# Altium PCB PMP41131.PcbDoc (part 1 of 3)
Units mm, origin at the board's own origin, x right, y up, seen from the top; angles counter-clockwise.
Board outline 53.98 x 39 mm, 6 copper layers (Top Layer, Signal Layer 1, Signal Layer 2, Signal Layer 3, Signal Layer 4, Bottom Layer), stack 1.835 mm thick; 91 components, 60 nets, 285 pads, 252 vias.
Unrouted connection lines stored in the file: 18.
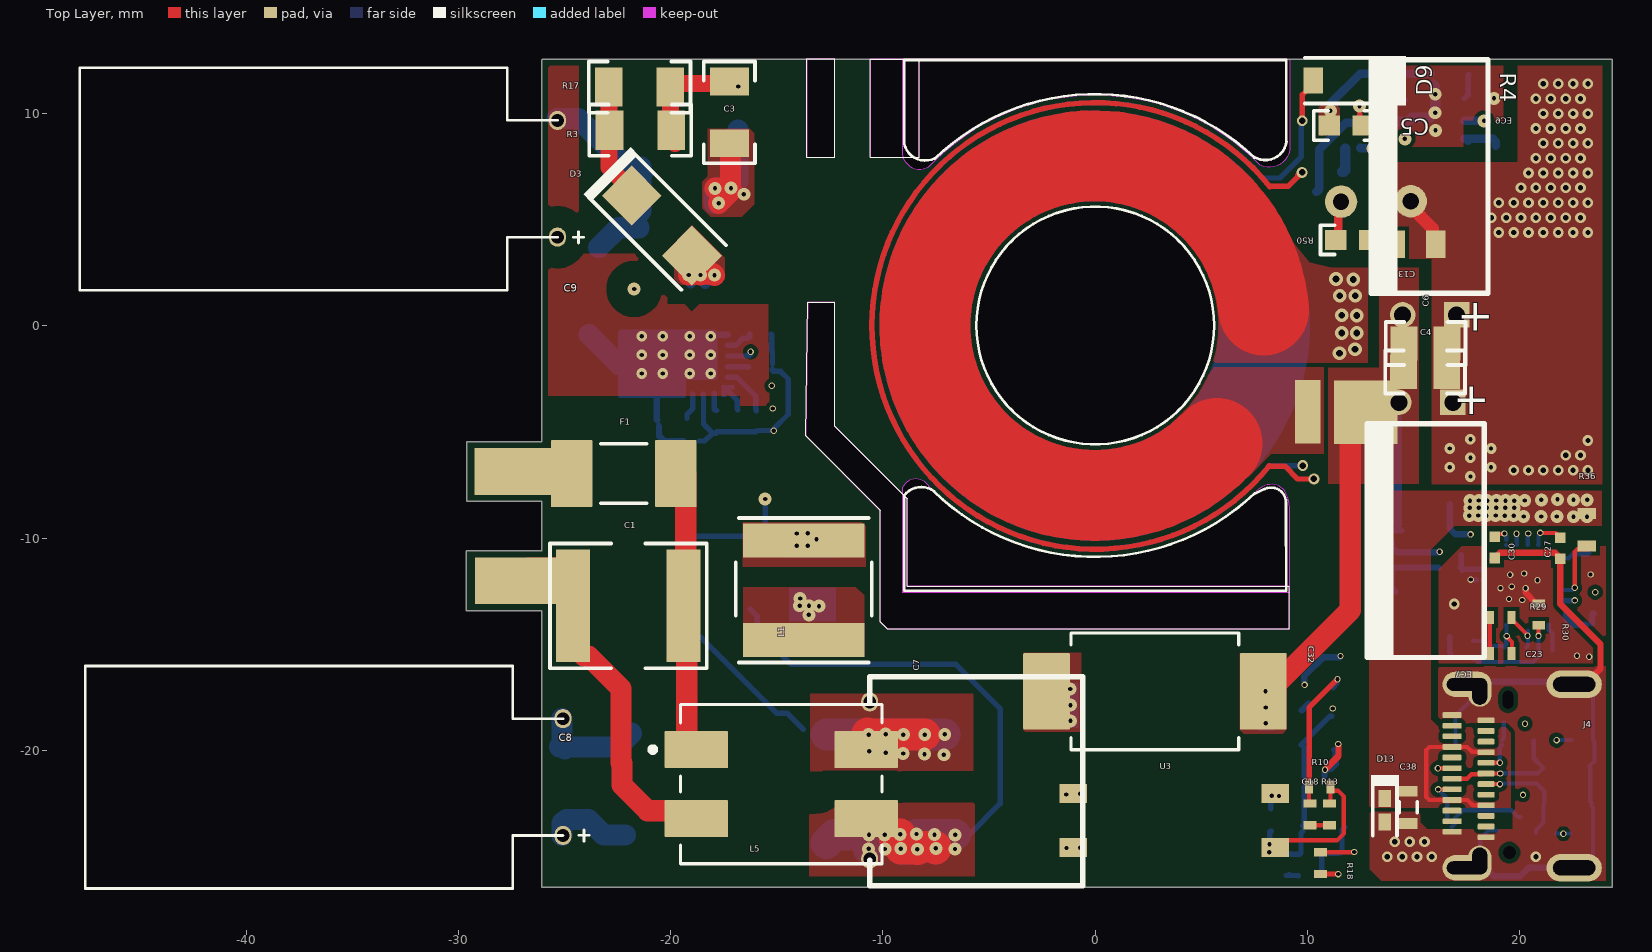
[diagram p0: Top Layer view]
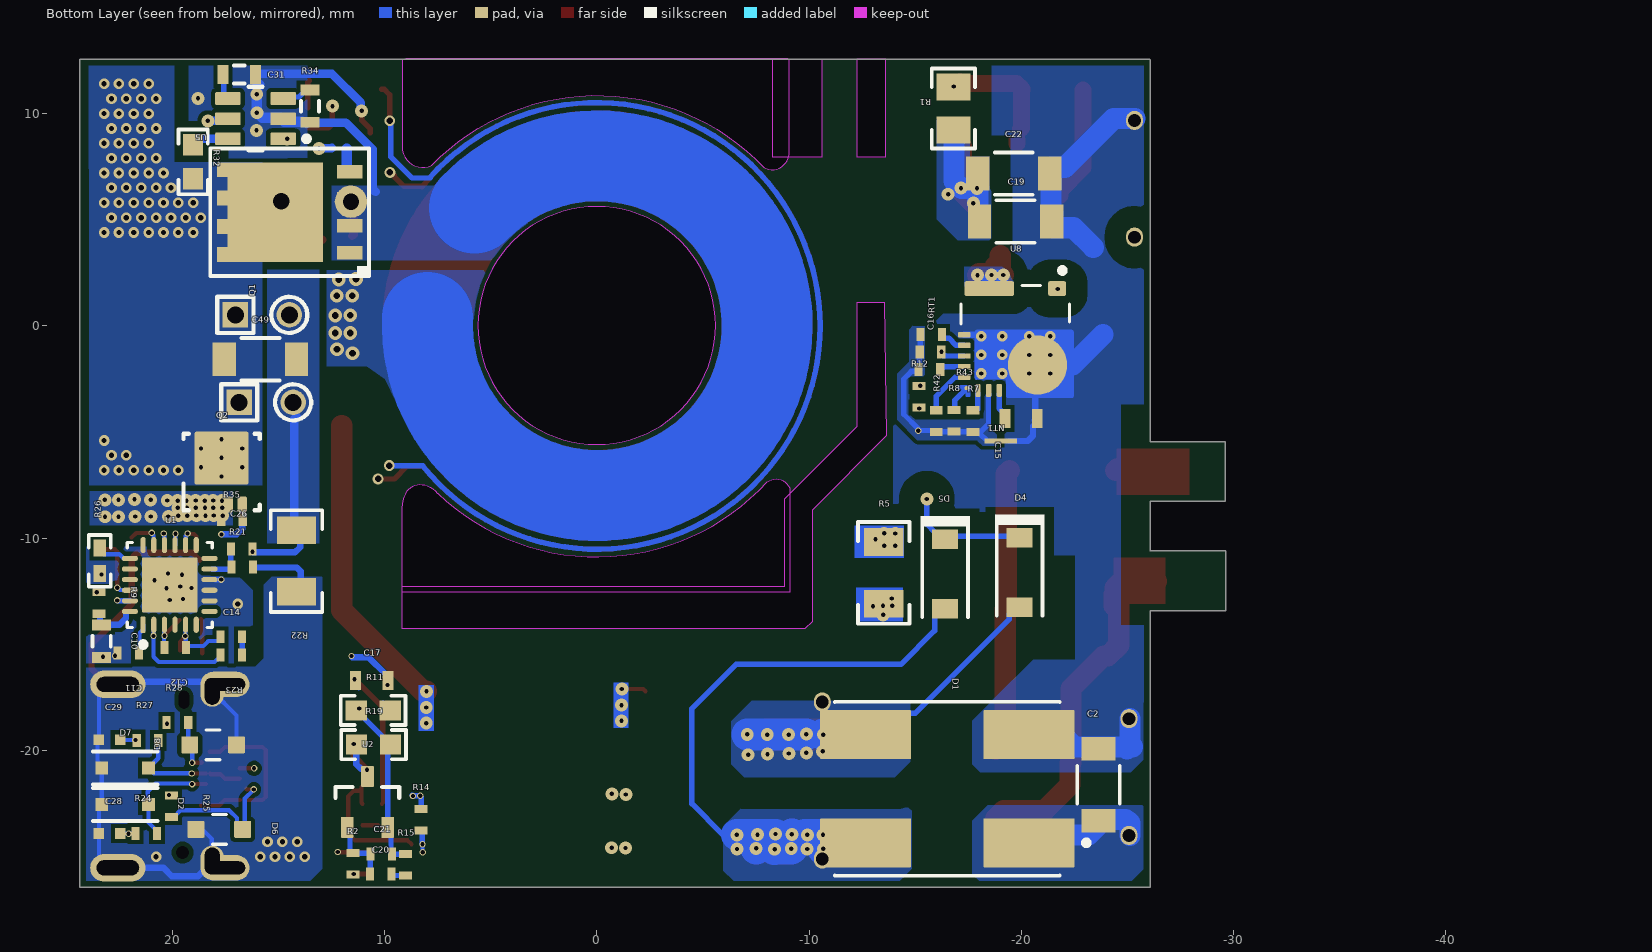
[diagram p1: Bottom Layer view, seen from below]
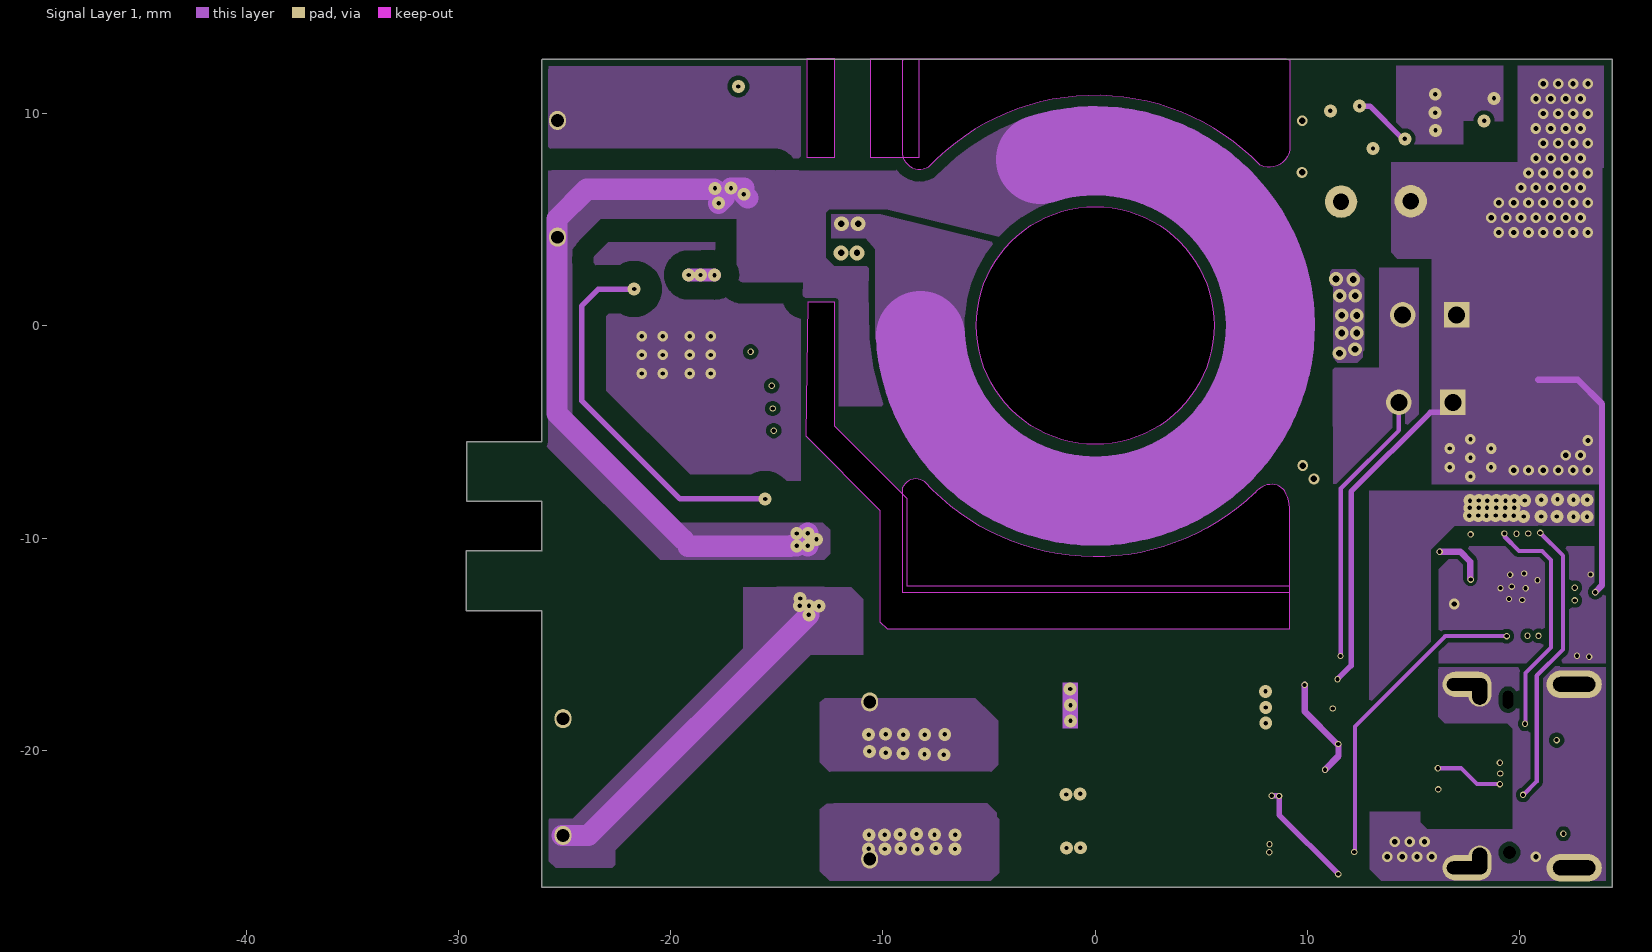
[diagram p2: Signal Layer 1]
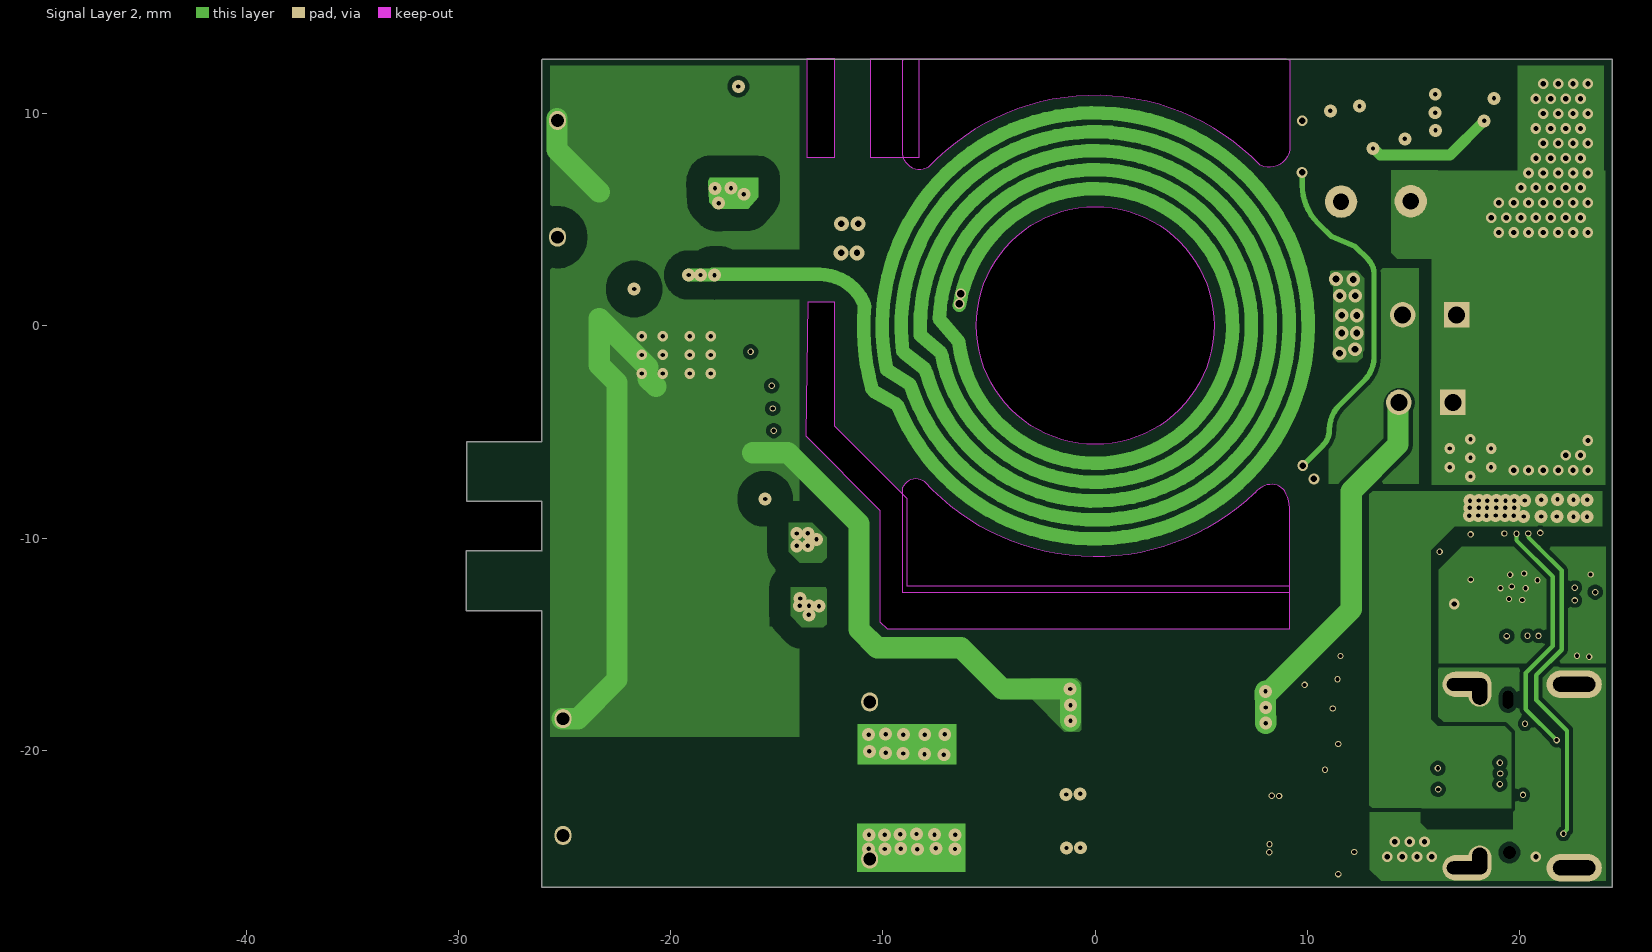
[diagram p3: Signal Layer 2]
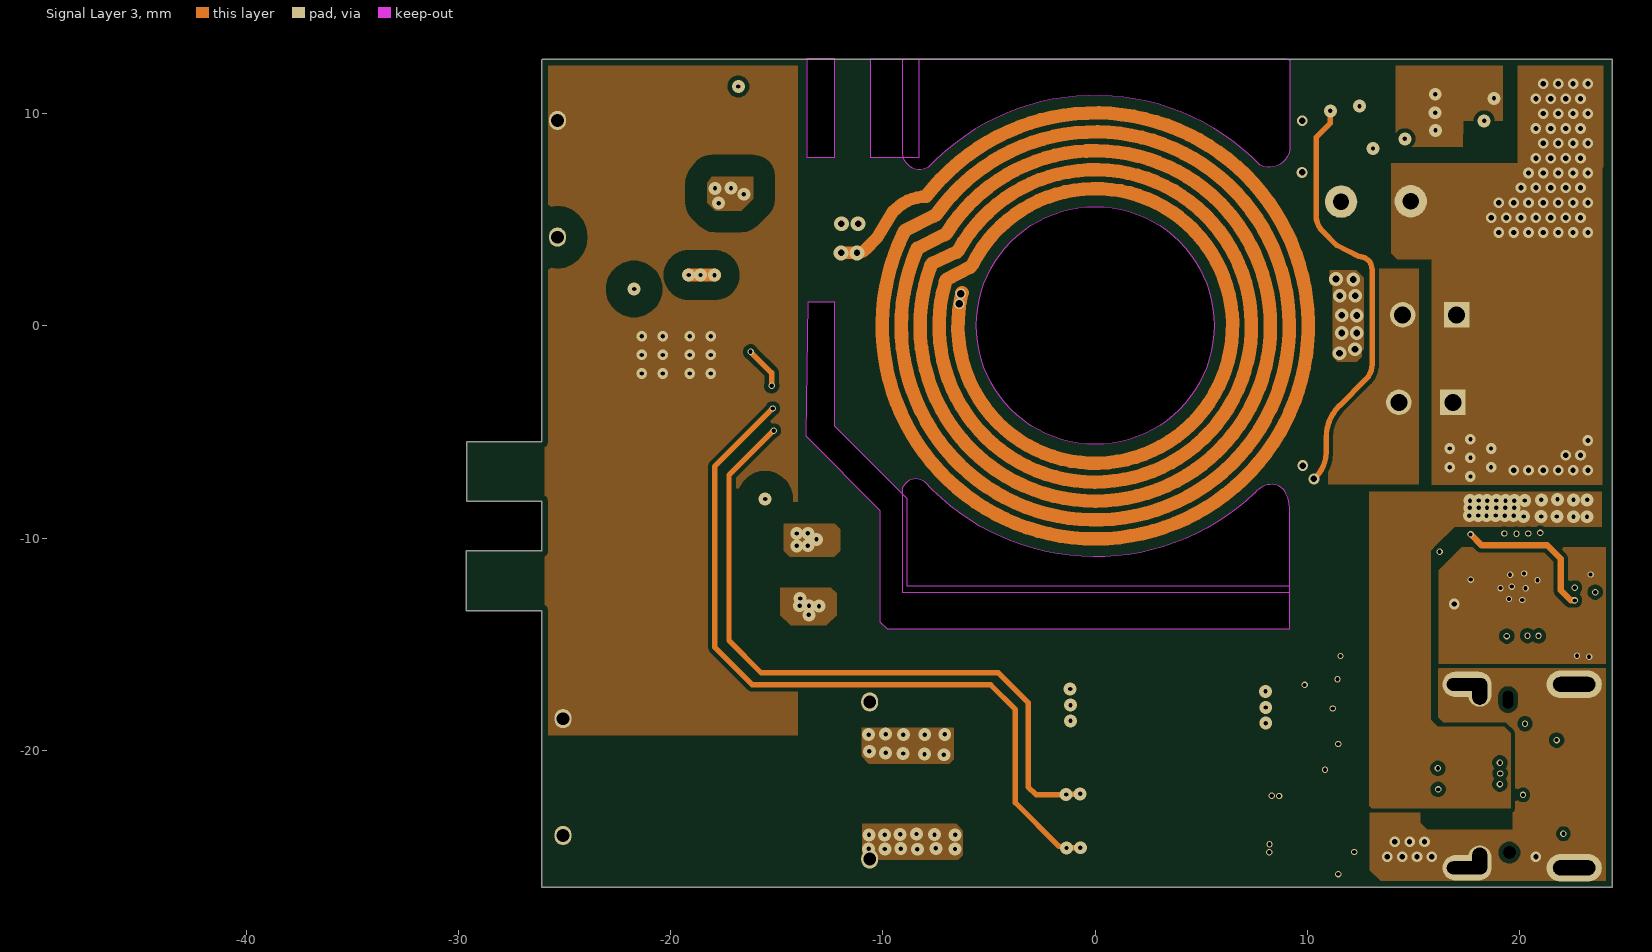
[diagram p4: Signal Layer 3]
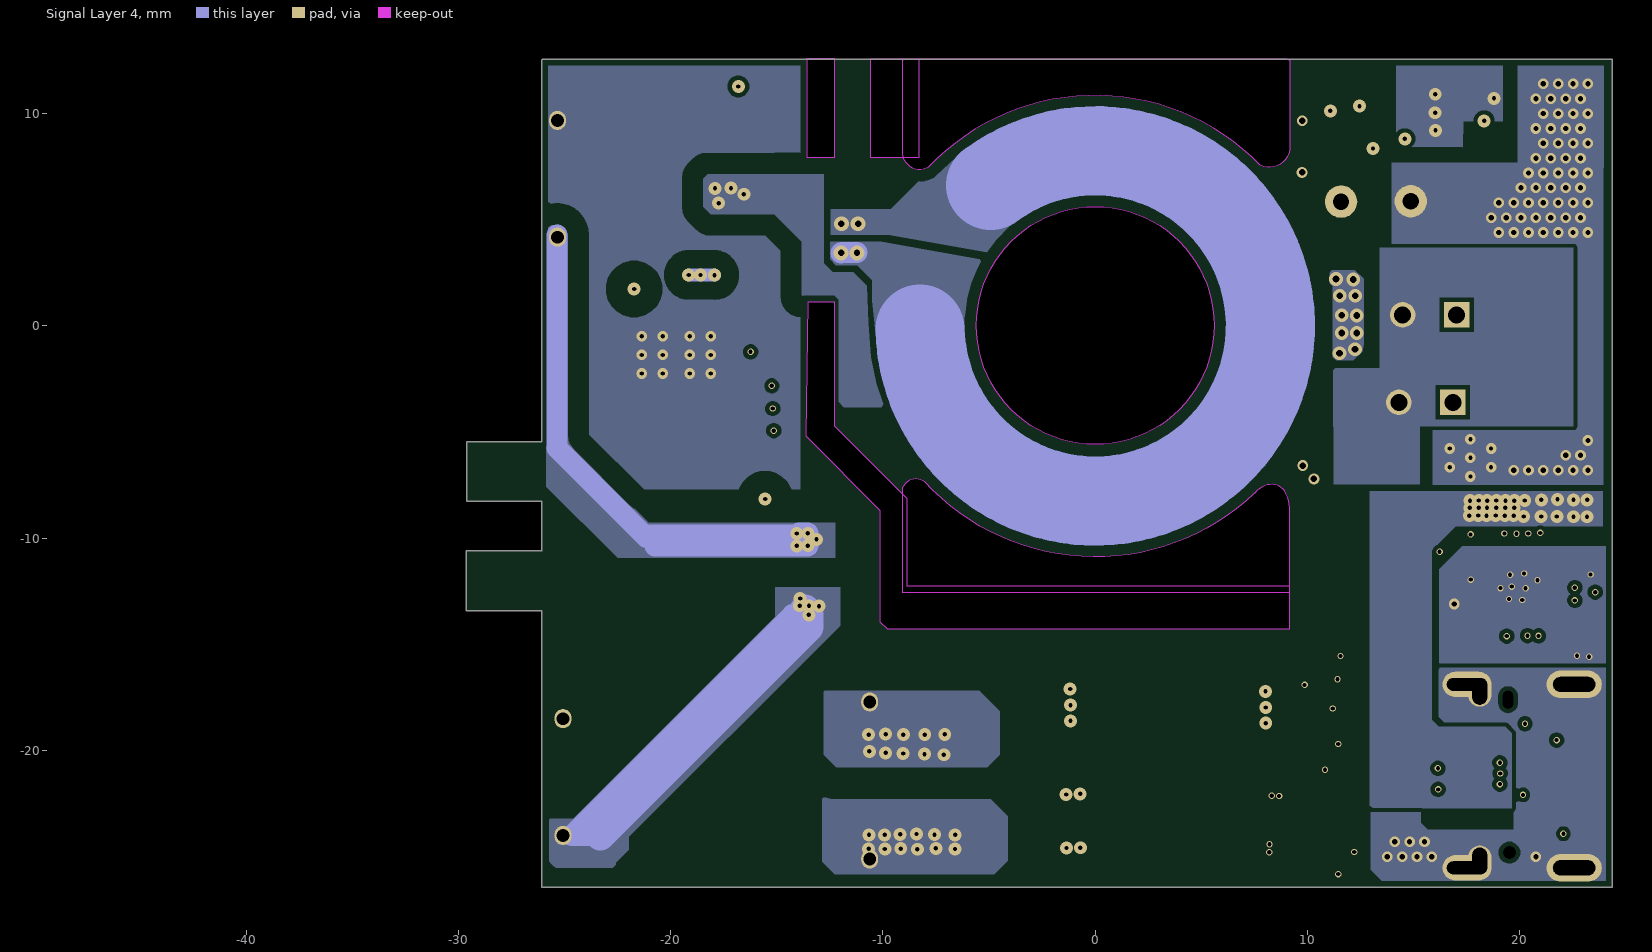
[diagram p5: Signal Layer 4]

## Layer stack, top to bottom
Top Solder: solder mask 0.0127, Solder Resist, Dk 3.5
Top Layer: signal copper 0.14
Dielectric 1: prepreg 0.1778, FR-4 High Tg, Dk 4.2
Signal Layer 1: signal copper 0.07
Dielectric 2: core 0.3556, FR-4 High Tg, Dk 4.2
Signal Layer 2: signal copper 0.07
Dielectric 4: prepreg 0.2083, FR-4 High Tg, Dk 4.2
Signal Layer 3: signal copper 0.07
Dielectric 5: core 0.3556, FR-4 High Tg, Dk 4.2
Signal Layer 4: signal copper 0.07
Dielectric 3: prepreg 0.1778, FR-4 High Tg, Dk 4.2
Bottom Layer: signal copper 0.14
Bottom Solder: solder mask 0.0127, Solder Resist, Dk 3.5

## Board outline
-29.63,-13.41 -29.63,-10.6 -26.08,-10.6 -26.06,-10.59 -26.06,-8.26 -29.61,-8.26 -29.61,-5.45 -26.06,-5.45 -26.06,12.543 -26.04,12.554 24.35,12.554 24.35,-26.45 -26.06,-26.45 -26.06,-26.436 -26.06,-13.41
cut-out: -7.857,7.483 cw(c-8.275,8.14) -9.018,7.907 -9.064,8.055 -9.064,8.579 -9.064,12.52 -9,12.584 9,12.584 9.166,12.52 9.166,8.436 cw(c8.194,8.442) 7.78,7.563 ccw(c0,0.02)
cut-out: -9.081,-12.539 9.155,-12.539 9.155,-8.567 ccw(c7.755,-8.547) 8.922,-7.773 ccw(c8.333,-8.198) 8.461,-7.483 ccw(c8.296,-8.309) 7.977,-7.529 ccw(c8.435,-8.63) 7.503,-7.887 7.498,-7.891 cw(c0,0.02) -8.036,-7.345 ccw(c-8.449,-7.894) -9.081,-7.624
cut-out: -10.227,34.327 cw(c-10.648,35.304) -11.685,35.069 -11.698,35.107 -11.698,39.037 -11.634,39.101 6.366,39.101 6.43,39.037 6.43,35.231 6.439,35.189 cw(c5.384,35.325) 4.89,34.383 4.825,34.397 ccw(c-2.634,26.537)
cut-out: 0,-5.58 cw(c0,0.02) -5.6,0.02 cw(c0,0.02) 0,5.62 cw(c0,0.02) 5.6,0.02 cw(c0,0.02)
cut-out: 0,-5.58 cw(c0,0.02) -5.6,0.02 cw(c0,0.02) 0,5.62 cw(c0,0.02) 5.6,0.02 cw(c0,0.02)
cut-out: -10.6,12.56 -10.6,7.94 -8.29,7.94 -8.29,12.56
cut-out: -13.59,12.592 -13.59,7.95 -12.26,7.95 -12.26,12.592
cut-out: -13.645,-5.18 -10.14,-8.685 -10.14,-13.925 -9.79,-14.275 9.15,-14.275 9.15,-12.265 -8.86,-12.265 -8.86,-8.145 -12.28,-4.725 -12.28,1.125 -13.548,1.125

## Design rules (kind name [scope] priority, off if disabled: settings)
AcuteAngle [All] p1: minimum=4.50000000000000E+0001 checktracksonly=FALSE
AssemblyTestPointUsage [All] p1: valid=2
BoardOutlineClearance BoardOutlineClearance_MountingHoles [OnCopper and InComponentClass('Mounting Holes')] p1: gap=0.3 ignorepadtopadclearanceinfootprint=FALSE
BoardOutlineClearance BoardOutlineClearance_Poly [OnCopper and IsPoly] p2: gap=0.3 ignorepadtopadclearanceinfootprint=FALSE
BoardOutlineClearance [OnCopper and Not InComponentClass('Logo') and not InComponentClass('FiducialMark') and not InRegion(1000,500,4000,800) and not InPoly] p3: gap=0.3 ignorepadtopadclearanceinfootprint=FALSE
Clearance Clearance_8 [InNamedPolygon('SIGNAL_LAYER_4_VBUS_P366')] p1: gap=0.55 ignorepadtopadclearanceinfootprint=FALSE
Clearance Clearance_7 [InNamedPolygon('SIGNAL_LAYER_1_VBUS_P372')] p2: gap=0.55 ignorepadtopadclearanceinfootprint=FALSE
Clearance Clearance_6 [InNamedPolygon('SIGNAL_LAYER_1_VBUS_P373')] p3: gap=0.55 ignorepadtopadclearanceinfootprint=FALSE
Clearance Clearance_5 [InNamedPolygon('SIGNAL_LAYER_4_VBUS_P371')] p4: gap=0.55 ignorepadtopadclearanceinfootprint=FALSE
Clearance Clearance_4 [InNamedPolygon('SIGNAL_LAYER_4_VBUS_P371')] p5: gap=0.55 ignorepadtopadclearanceinfootprint=FALSE
Clearance Clearance_2 [InNamedPolygon('SIGNAL_LAYER_1_VBUS_P373')] p6: gap=0.55 ignorepadtopadclearanceinfootprint=FALSE
Clearance [InNamedPolygon('SIGNAL_LAYER_1_VBUS_P373')] p7: gap=0.55 ignorepadtopadclearanceinfootprint=FALSE
Clearance Clearance_3 [InNamedPolygon('SIGNAL_LAYER_1_VBUS_P373')] p8: gap=0.6 ignorepadtopadclearanceinfootprint=FALSE
Clearance Clearance_VAC_PGND [InNetClass('VAC') vs InNetClass('PGND')] p9: gap=2 ignorepadtopadclearanceinfootprint=TRUE
Clearance Clearance_HV_PGND [InNetClass('High Voltage') vs InNetClass('PGND')] p10: gap=1.016 ignorepadtopadclearanceinfootprint=TRUE
Clearance Clearance_SW_PGND [InNetClass('Switch Node') vs InNetClass('PGND')] p11: gap=0.864 ignorepadtopadclearanceinfootprint=TRUE
Clearance Clearance_AC_AC [InNetClass('VAC') vs InNetClass('VAC')] p12: gap=1.5 ignorepadtopadclearanceinfootprint=TRUE
Clearance Clearance_PGND_SGND [InNetClass('PGND') vs InNetClass('SGND')] p13: gap=4.064 ignorepadtopadclearanceinfootprint=TRUE
Clearance Clearance_HV_LV [InNetClass('High Voltage') vs InNetClass('Low Voltage')] p14: gap=0.864 ignorepadtopadclearanceinfootprint=TRUE
Clearance Clearance_SW_LV_1 [InNetClass('Switch Node') vs InNetClass('Low Voltage')] p15: gap=0.864 ignorepadtopadclearanceinfootprint=TRUE
Clearance Clearance_SW_HV [InNetClass('Switch Node') vs InNetClass('High Voltage')] p16: gap=0.864 ignorepadtopadclearanceinfootprint=TRUE
Clearance Clearance_1 [All] p17: gap=0.2 ignorepadtopadclearanceinfootprint=TRUE
Clearance Clearance_Keepouts [((IsTrack Or IsArc) And Not InPoly) And IsFree and IsKeepOut vs ((IsTrack Or IsArc) And Not InPoly) And IsFree and IsKeepOut] p18: gap=0.254 ignorepadtopadclearanceinfootprint=FALSE
Clearance Clearance_Poly [InPolygon] p19: gap=0.254 ignorepadtopadclearanceinfootprint=TRUE
Clearance Clearance_FiducialMark [IsKeepOut and InComponentClass('FiducialMark') vs IsPad and InComponentClass('FiducialMark')] p20: gap=0.254 ignorepadtopadclearanceinfootprint=FALSE
ComponentClearance ComponentClearance_MountingHoles_FiducialMarks [InComponentClass('Mounting Holes') vs InComponentClass('FiducialMark')] p1: gap=0.2 collisioncheckmode=3 verticalgap=0.2 showdistances=FALSE
ComponentClearance ComponentClearance_Shunt [InComponentClass('Header') vs InComponentClass('Shunt')] p2: gap=0 collisioncheckmode=3 verticalgap=0 showdistances=FALSE
ComponentClearance ComponentClearance_Logo [InComponentClass('Logo')] p3: gap=0.2 collisioncheckmode=3 verticalgap=0.2 showdistances=FALSE
ComponentClearance ComponentClearance_ScrewToNut [(HasFootprint('NY PMS 440 0025 PH')) vs (HasFootprint('Keystone_1902C'))] p4: gap=0.127 collisioncheckmode=3 verticalgap=0.254 showdistances=FALSE
ComponentClearance ComponentClearance_MountingHoles [InComponentClass('Mounting Holes')] p5: gap=1 collisioncheckmode=3 verticalgap=2540 showdistances=FALSE
ComponentClearance ComponentClearance_SmallPassives [HasFootprint('0201*') or HasFootprint('0402*') or HasFootprint('0508') or HasFootprint('0603*') or HasFootprint('0612') or HasFootprint('0805*') or HasFootprint('0815*') or HasFootprint('0830*') or HasFootprint('1206*') or HasFootprint('1210*') or HasFootprint('1808*') or HasFootprint('1812*') or HasFootprint('1825*') or HasFootprint('2010*') or HasFootprint('2220*') or HasFootprint('2225*') or HasFootprint('2512*') or HasFootprint('2728*') or HasFootprint('3518*') vs HasFootprint('0201*') or HasFootprint('0402*') or HasFootprint('0508') or HasFootprint('0603*') or HasFootprint('0612') or HasFootprint('0805*') or HasFootprint('0815*') or HasFootprint('0830*') or HasFootprint('1206*') or HasFootprint('1210*') or HasFootprint('1808*') or HasFootprint('1812*') or HasFootprint('1825*') or HasFootprint('2010*') or HasFootprint('2220*') or HasFootprint('2225*') or HasFootprint('2512*') or HasFootprint('2728*') or HasFootprint('3518*')] p6: gap=0.2 collisioncheckmode=3 verticalgap=0.2 showdistances=FALSE
ComponentClearance ComponentClearance_THtoSMT [IsThruComponent vs IsSMTComponent] p7: gap=0.2 collisioncheckmode=3 verticalgap=0.2 showdistances=FALSE
ComponentClearance ComponentClearance_THtoTH [IsThruComponent vs IsThruComponent] p8: gap=0.2 collisioncheckmode=3 verticalgap=0.2 showdistances=FALSE
ComponentClearance [All] p9: gap=0.1 collisioncheckmode=3 verticalgap=0.1 showdistances=FALSE
DiffPairsRouting DiffPair_DiffPairsRouting [All] p1: maxlimit=0.254 minlimit=0.254 mostfreqgap=0.254 toplayer_minwidth=0.254 toplayer_maxwidth=0.254 toplayer_prefwidth=0.254 midlayer1_minwidth=0.254 midlayer1_maxwidth=0.254 midlayer1_prefwidth=0.254 midlayer2_minwidth=0.254 midlayer2_maxwidth=0.254 midlayer2_prefwidth=0.254 midlayer3_minwidth=0.254 midlayer3_maxwidth=0.254 midlayer3_prefwidth=0.254 midlayer4_minwidth=0.254 midlayer4_maxwidth=0.254 midlayer4_prefwidth=0.254 bottomlayer_minwidth=0.254 bottomlayer_maxwidth=0.254 bottomlayer_prefwidth=0.254 filterlayerstackid={9F2BDCAB-BF4A-4FAE-9F57-695CEC5DA6CF} maxuncoupledlength=12.7
DiffPairsRouting DiffPair_DiffPairsRouting_1 [InDifferentialPair ('NewDifferentialPair1')] p2: maxlimit=0.203 minlimit=0.203 mostfreqgap=0.203 toplayer_minwidth=0.254 toplayer_maxwidth=0.254 toplayer_prefwidth=0.254 midlayer1_minwidth=0.254 midlayer1_maxwidth=0.254 midlayer1_prefwidth=0.254 midlayer2_minwidth=0.254 midlayer2_maxwidth=0.254 midlayer2_prefwidth=0.254 midlayer3_minwidth=0.254 midlayer3_maxwidth=0.254 midlayer3_prefwidth=0.254 midlayer4_minwidth=0.254 midlayer4_maxwidth=0.254 midlayer4_prefwidth=0.254 bottomlayer_minwidth=0.254 bottomlayer_maxwidth=0.254 bottomlayer_prefwidth=0.254 filterlayerstackid={9F2BDCAB-BF4A-4FAE-9F57-695CEC5DA6CF} maxuncoupledlength=12.7
DiffPairsRouting DiffPair_DiffPairsRouting_2 [InDifferentialPair ('NewDifferentialPair1')] p3: maxlimit=0.127 minlimit=0.127 mostfreqgap=0.127 toplayer_minwidth=0.254 toplayer_maxwidth=0.254 toplayer_prefwidth=0.254 midlayer1_minwidth=0.254 midlayer1_maxwidth=0.254 midlayer1_prefwidth=0.254 midlayer2_minwidth=0.254 midlayer2_maxwidth=0.254 midlayer2_prefwidth=0.254 midlayer3_minwidth=0.254 midlayer3_maxwidth=0.254 midlayer3_prefwidth=0.254 midlayer4_minwidth=0.254 midlayer4_maxwidth=0.254 midlayer4_prefwidth=0.254 bottomlayer_minwidth=0.254 bottomlayer_maxwidth=0.254 bottomlayer_prefwidth=0.254 filterlayerstackid={9F2BDCAB-BF4A-4FAE-9F57-695CEC5DA6CF} maxuncoupledlength=12.7
DiffPairsRouting DiffPair_DiffPairsRouting_3 [InDifferentialPair ('NewDifferentialPair1')] p4: maxlimit=0.178 minlimit=0.178 mostfreqgap=0.178 toplayer_minwidth=0.254 toplayer_maxwidth=0.254 toplayer_prefwidth=0.254 midlayer1_minwidth=0.254 midlayer1_maxwidth=0.254 midlayer1_prefwidth=0.254 midlayer2_minwidth=0.254 midlayer2_maxwidth=0.254 midlayer2_prefwidth=0.254 midlayer3_minwidth=0.254 midlayer3_maxwidth=0.254 midlayer3_prefwidth=0.254 midlayer4_minwidth=0.254 midlayer4_maxwidth=0.254 midlayer4_prefwidth=0.254 bottomlayer_minwidth=0.254 bottomlayer_maxwidth=0.254 bottomlayer_prefwidth=0.254 filterlayerstackid={9F2BDCAB-BF4A-4FAE-9F57-695CEC5DA6CF} maxuncoupledlength=12.7
DiffPairsRouting DiffPair_DiffPairsRouting_4 [InDifferentialPair ('NewDifferentialPair1')] p5: maxlimit=0.254 minlimit=0.254 mostfreqgap=0.254 toplayer_minwidth=0.381 toplayer_maxwidth=0.381 toplayer_prefwidth=0.381 midlayer1_minwidth=0.381 midlayer1_maxwidth=0.381 midlayer1_prefwidth=0.381 midlayer2_minwidth=0.381 midlayer2_maxwidth=0.381 midlayer2_prefwidth=0.381 midlayer3_minwidth=0.381 midlayer3_maxwidth=0.381 midlayer3_prefwidth=0.381 midlayer4_minwidth=0.381 midlayer4_maxwidth=0.381 midlayer4_prefwidth=0.381 bottomlayer_minwidth=0.381 bottomlayer_maxwidth=0.381 bottomlayer_prefwidth=0.381 filterlayerstackid={9F2BDCAB-BF4A-4FAE-9F57-695CEC5DA6CF} maxuncoupledlength=12.7
DiffPairsRouting DiffPair_DiffPairsRouting_5 [All] p6: maxlimit=0.254 minlimit=0.254 mostfreqgap=0.254 toplayer_minwidth=0.254 toplayer_maxwidth=0.254 toplayer_prefwidth=0.254 midlayer1_minwidth=0.254 midlayer1_maxwidth=0.254 midlayer1_prefwidth=0.254 midlayer2_minwidth=0.254 midlayer2_maxwidth=0.254 midlayer2_prefwidth=0.254 midlayer3_minwidth=0.254 midlayer3_maxwidth=0.254 midlayer3_prefwidth=0.254 midlayer4_minwidth=0.254 midlayer4_maxwidth=0.254 midlayer4_prefwidth=0.254 bottomlayer_minwidth=0.254 bottomlayer_maxwidth=0.254 bottomlayer_prefwidth=0.254 filterlayerstackid={9F2BDCAB-BF4A-4FAE-9F57-695CEC5DA6CF} maxuncoupledlength=12.7
DiffPairsRouting DiffPair_DiffPairsRouting_6 [All] p7: maxlimit=0.254 minlimit=0.254 mostfreqgap=0.254 toplayer_minwidth=0.254 toplayer_maxwidth=0.254 toplayer_prefwidth=0.254 midlayer1_minwidth=0.254 midlayer1_maxwidth=0.254 midlayer1_prefwidth=0.254 midlayer2_minwidth=0.254 midlayer2_maxwidth=0.254 midlayer2_prefwidth=0.254 midlayer3_minwidth=0.254 midlayer3_maxwidth=0.254 midlayer3_prefwidth=0.254 midlayer4_minwidth=0.254 midlayer4_maxwidth=0.254 midlayer4_prefwidth=0.254 bottomlayer_minwidth=0.254 bottomlayer_maxwidth=0.254 bottomlayer_prefwidth=0.254 filterlayerstackid={9F2BDCAB-BF4A-4FAE-9F57-695CEC5DA6CF} maxuncoupledlength=12.7
DiffPairsRouting DiffPair_DiffPairsRouting_7 [InDifferentialPair ('NewDifferentialPair2')] p8: maxlimit=0.254 minlimit=0.254 mostfreqgap=0.254 toplayer_minwidth=0.254 toplayer_maxwidth=0.254 toplayer_prefwidth=0.254 midlayer1_minwidth=0.254 midlayer1_maxwidth=0.254 midlayer1_prefwidth=0.254 midlayer2_minwidth=0.254 midlayer2_maxwidth=0.254 midlayer2_prefwidth=0.254 midlayer3_minwidth=0.254 midlayer3_maxwidth=0.254 midlayer3_prefwidth=0.254 midlayer4_minwidth=0.254 midlayer4_maxwidth=0.254 midlayer4_prefwidth=0.254 bottomlayer_minwidth=0.254 bottomlayer_maxwidth=0.254 bottomlayer_prefwidth=0.254 filterlayerstackid={9F2BDCAB-BF4A-4FAE-9F57-695CEC5DA6CF} maxuncoupledlength=12.7
DiffPairsRouting DiffPair_DiffPairsRouting_8 [InDifferentialPair ('NewDifferentialPair2')] p9: maxlimit=0.254 minlimit=0.254 mostfreqgap=0.254 toplayer_minwidth=0.381 toplayer_maxwidth=0.381 toplayer_prefwidth=0.381 midlayer1_minwidth=0.381 midlayer1_maxwidth=0.381 midlayer1_prefwidth=0.381 midlayer2_minwidth=0.381 midlayer2_maxwidth=0.381 midlayer2_prefwidth=0.381 midlayer3_minwidth=0.381 midlayer3_maxwidth=0.381 midlayer3_prefwidth=0.381 midlayer4_minwidth=0.381 midlayer4_maxwidth=0.381 midlayer4_prefwidth=0.381 bottomlayer_minwidth=0.381 bottomlayer_maxwidth=0.381 bottomlayer_prefwidth=0.381 filterlayerstackid={9F2BDCAB-BF4A-4FAE-9F57-695CEC5DA6CF} maxuncoupledlength=12.7
DiffPairsRouting DiffPair_DiffPairsRouting_9 [InDifferentialPair ('ISense_A')] p10: maxlimit=0.198 minlimit=0.198 mostfreqgap=0.198 toplayer_minwidth=0.254 toplayer_maxwidth=0.254 toplayer_prefwidth=0.254 midlayer1_minwidth=0.254 midlayer1_maxwidth=0.254 midlayer1_prefwidth=0.254 midlayer2_minwidth=0.254 midlayer2_maxwidth=0.254 midlayer2_prefwidth=0.254 midlayer3_minwidth=0.254 midlayer3_maxwidth=0.254 midlayer3_prefwidth=0.254 midlayer4_minwidth=0.254 midlayer4_maxwidth=0.254 midlayer4_prefwidth=0.254 bottomlayer_minwidth=0.254 bottomlayer_maxwidth=0.254 bottomlayer_prefwidth=0.254 filterlayerstackid={9F2BDCAB-BF4A-4FAE-9F57-695CEC5DA6CF} maxuncoupledlength=12.7
DiffPairsRouting DiffPair_DiffPairsRouting_10 [InDifferentialPair ('ISense_A')] p11: maxlimit=0.254 minlimit=0.254 mostfreqgap=0.254 toplayer_minwidth=0.381 toplayer_maxwidth=0.381 toplayer_prefwidth=0.381 midlayer1_minwidth=0.381 midlayer1_maxwidth=0.381 midlayer1_prefwidth=0.381 midlayer2_minwidth=0.381 midlayer2_maxwidth=0.381 midlayer2_prefwidth=0.381 midlayer3_minwidth=0.381 midlayer3_maxwidth=0.381 midlayer3_prefwidth=0.381 midlayer4_minwidth=0.381 midlayer4_maxwidth=0.381 midlayer4_prefwidth=0.381 bottomlayer_minwidth=0.381 bottomlayer_maxwidth=0.381 bottomlayer_prefwidth=0.381 filterlayerstackid={9F2BDCAB-BF4A-4FAE-9F57-695CEC5DA6CF} maxuncoupledlength=12.7
DiffPairsRouting DiffPair_DiffPairsRouting_11 [InDifferentialPair ('ISense_A')] p12: maxlimit=0.254 minlimit=0.254 mostfreqgap=0.254 toplayer_minwidth=0.381 toplayer_maxwidth=0.381 toplayer_prefwidth=0.381 midlayer1_minwidth=0.381 midlayer1_maxwidth=0.381 midlayer1_prefwidth=0.381 midlayer2_minwidth=0.381 midlayer2_maxwidth=0.381 midlayer2_prefwidth=0.381 midlayer3_minwidth=0.381 midlayer3_maxwidth=0.381 midlayer3_prefwidth=0.381 midlayer4_minwidth=0.381 midlayer4_maxwidth=0.381 midlayer4_prefwidth=0.381 bottomlayer_minwidth=0.381 bottomlayer_maxwidth=0.381 bottomlayer_prefwidth=0.381 filterlayerstackid={9F2BDCAB-BF4A-4FAE-9F57-695CEC5DA6CF} maxuncoupledlength=12.7
DiffPairsRouting DiffPair_ADiffPairsRouting [All] p13: maxlimit=0.198 minlimit=0.198 mostfreqgap=0.198 toplayer_minwidth=0.254 toplayer_maxwidth=0.254 toplayer_prefwidth=0.254 midlayer1_minwidth=0.254 midlayer1_maxwidth=0.254 midlayer1_prefwidth=0.254 midlayer2_minwidth=0.254 midlayer2_maxwidth=0.254 midlayer2_prefwidth=0.254 midlayer3_minwidth=0.254 midlayer3_maxwidth=0.254 midlayer3_prefwidth=0.254 midlayer4_minwidth=0.254 midlayer4_maxwidth=0.254 midlayer4_prefwidth=0.254 bottomlayer_minwidth=0.254 bottomlayer_maxwidth=0.254 bottomlayer_prefwidth=0.254 filterlayerstackid={9F2BDCAB-BF4A-4FAE-9F57-695CEC5DA6CF} maxuncoupledlength=12.7
DiffPairsRouting [All] p14: maxlimit=2.54 minlimit=0.254 mostfreqgap=0.254 toplayer_minwidth=0.381 toplayer_maxwidth=0.381 toplayer_prefwidth=0.381 midlayer1_minwidth=0.381 midlayer1_maxwidth=0.381 midlayer1_prefwidth=0.381 midlayer2_minwidth=0.381 midlayer2_maxwidth=0.381 midlayer2_prefwidth=0.381 midlayer3_minwidth=0.381 midlayer3_maxwidth=0.381 midlayer3_prefwidth=0.381 midlayer4_minwidth=0.381 midlayer4_maxwidth=0.381 midlayer4_prefwidth=0.381 bottomlayer_minwidth=0.381 bottomlayer_maxwidth=0.381 bottomlayer_prefwidth=0.381 maxuncoupledlength=25.4
FabricationTestPointUsage TestPointUsage [All] p1: valid=2 allowmultiple=FALSE
FabricationTestpoint Testpoint [All] p1: side=3 testpointundercomponent=TRUE minsize=1.016 maxsize=2.54 preferedsize=1.524 minholesize=0 maxholesize=1.016 preferedholesize=0.813 testpointgrid=0.025 allowsidetop=TRUE allowsidebottom=TRUE usegrid=TRUE gridtolerance=0
FanoutControl Fanout_LCC [IsLCC] p1: bgadir=Out bgaviamode=Centered fanoutstyle=Auto fanoutdirection=Alternating viagrid=0.025 // Fanout_LCC (Default Rule)
FanoutControl Fanout_BGA [IsBGA] p2: bgadir=Out bgaviamode=Centered fanoutstyle=Auto fanoutdirection=Alternating viagrid=0.025 // Fanout_BGA (Default Rule)
HoleSize [All] p1: absolutevalues=TRUE maxlimit=6.375 minlimit=0.2 maxpercent=80.000 minpercent=20.000
MatchedLengths DiffPair_MatchedLengths [All] p1: tolerance=25.4 checknetsindiffpair=FALSE checkdiffpairvsdiffpair=TRUE checkxsignals=TRUE checkothers=TRUE
MatchedLengths DiffPair_MatchedLengths_1 [InDifferentialPair ('NewDifferentialPair1')] p2: tolerance=25.4 checknetsindiffpair=FALSE checkdiffpairvsdiffpair=TRUE checkxsignals=TRUE checkothers=TRUE
MatchedLengths DiffPair_MatchedLengths_2 [InDifferentialPair ('NewDifferentialPair1')] p3: tolerance=25.4 checknetsindiffpair=FALSE checkdiffpairvsdiffpair=TRUE checkxsignals=TRUE checkothers=TRUE
MatchedLengths DiffPair_MatchedLengths_3 [InDifferentialPair ('NewDifferentialPair1')] p4: tolerance=25.4 checknetsindiffpair=FALSE checkdiffpairvsdiffpair=TRUE checkxsignals=TRUE checkothers=TRUE
MatchedLengths DiffPair_MatchedLengths_4 [InDifferentialPair ('NewDifferentialPair1')] p5: tolerance=25.4 checknetsindiffpair=FALSE checkdiffpairvsdiffpair=TRUE checkxsignals=TRUE checkothers=TRUE
MatchedLengths DiffPair_MatchedLengths_5 [All] p6: tolerance=25.4 checknetsindiffpair=FALSE checkdiffpairvsdiffpair=TRUE checkxsignals=TRUE checkothers=TRUE
MatchedLengths DiffPair_MatchedLengths_6 [All] p7: tolerance=25.4 checknetsindiffpair=FALSE checkdiffpairvsdiffpair=TRUE checkxsignals=TRUE checkothers=TRUE
MatchedLengths DiffPair_MatchedLengths_7 [InDifferentialPair ('NewDifferentialPair2')] p8: tolerance=25.4 checknetsindiffpair=FALSE checkdiffpairvsdiffpair=TRUE checkxsignals=TRUE checkothers=TRUE
MatchedLengths DiffPair_MatchedLengths_8 [InDifferentialPair ('NewDifferentialPair2')] p9: tolerance=25.4 checknetsindiffpair=FALSE checkdiffpairvsdiffpair=TRUE checkxsignals=TRUE checkothers=TRUE
MatchedLengths DiffPair_MatchedLengths_9 [InDifferentialPair ('ISense_A')] p10: tolerance=25.4 checknetsindiffpair=FALSE checkdiffpairvsdiffpair=TRUE checkxsignals=TRUE checkothers=TRUE
MatchedLengths DiffPair_MatchedLengths_10 [InDifferentialPair ('ISense_A')] p11: tolerance=25.4 checknetsindiffpair=FALSE checkdiffpairvsdiffpair=TRUE checkxsignals=TRUE checkothers=TRUE
MatchedLengths DiffPair_MatchedLengths_11 [InDifferentialPair ('ISense_A')] p12: tolerance=25.4 checknetsindiffpair=FALSE checkdiffpairvsdiffpair=TRUE checkxsignals=TRUE checkothers=TRUE
MatchedLengths DiffPair_AMatchedLengths [All] p13: tolerance=25.4 checknetsindiffpair=FALSE checkdiffpairvsdiffpair=TRUE checkxsignals=TRUE checkothers=TRUE
MinimumAnnularRing MinimumAnnularRing_ThermalPadVias [IsVia and InAnyComponent] p1: minimumring=0.15
MinimumAnnularRing [All] p2: minimumring=0.2
MinimumSolderMaskSliver MinimumSolderMaskSliver_Logo [InComponentClass('Logo') vs InComponentClass('Logo')] p1: minsoldermaskwidth=0.018
MinimumSolderMaskSliver [All] p2: minsoldermaskwidth=0.1
PlaneConnect [All] p1: planeconnectstyle=Relief reliefexpansion=0.254 reliefentries=4 reliefconductorwidth=0.254 reliefairgap=0.254
PolygonConnect [All] p1: connectstyle=Direct reliefconductorwidth=0.254 reliefentries=4 polygonreliefangle="90 Angle" airgapwidth=0
RoutingLayers [All] p1 off: top layer_v5=TRUE mid layer 1_v5=TRUE mid layer 2_v5=TRUE mid layer 3_v5=TRUE mid layer 4_v5=TRUE bottom layer_v5=TRUE
RoutingVias "Buried Via" [IsBuriedVia] p1: holewidth=0.711 width=1.27 viastyle="Through Hole" minholewidth=0.711 minwidth=1.27 maxholewidth=0.711 maxwidth=1.27
RoutingVias ThermalPadVias [IsVia and InAnyComponent] p2: holewidth=0.2 width=0.5 viastyle="Through Hole" minholewidth=0.2 minwidth=0.5 maxholewidth=0.33 maxwidth=0.6
RoutingVias [All] p3: holewidth=0.406 width=0.864 viastyle="Through Hole" minholewidth=0.2 minwidth=0.61 maxholewidth=1.016 maxwidth=1.651
SilkToSilkClearance SilkToSilkClearance_Pb-FreeLogo [(HasFootprint('Pb-Free_Overlay_Medium') OR HasFootprint('Pb-Free_Overlay_Small')) vs (HasFootprint('Pb-Free_Overlay_Medium') OR HasFootprint('Pb-Free_Overlay_Small'))] p1: silktosilkclearance=0
SilkToSilkClearance [All] p2: silktosilkclearance=0.1
SilkToSolderMaskClearance SilkToComponentPadClearance [(IsPad or IsFill or IsRegion) and InAnycomponent] p1: minsilkscreentomaskgap=0.127 clearancetoexposedcopper=TRUE
SilkToSolderMaskClearance "Silk to Solder Mask Opening" [All] p2: minsilkscreentomaskgap=0.1 clearancetoexposedcopper=FALSE
SolderMaskExpansion [All] p1: expansion=0.05 istentingtop=FALSE
UnRoutedNet [All] p1: checkbadconnections=TRUE
Width [All] p1: maxlimit=2.54 minlimit=0.152 preferedwidth=0.2 checkconnectedcopper=TRUE
16 further rules are at their usual default settings.

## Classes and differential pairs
component class "USB Type C and PD": C10 C11 C12 C14 C23 C26 C27 C28 C29 C30 C38 C49 D2 D6 D7 D8 D13 J4 Q2 R9 R21 R22 R23 R24 R25 R26 R27 R28 R29 R30 R35 R36 U1
net class VAC: LINE NetC1_1 NetC7_1 NetC7_2 Neture
net class "Switch Node": VSW
net class SGND: SGND VO_ACDC
net class PGND: PGND
net class "High Voltage": NetC2_1 NetD4_1 Vbus
component class "AC DC": C1 C2 C3 C4 C5 C6 C7 C8 C9 C13 C15 C16 C17 C18 C19 C20 C21 C22 C31 C32 D1 D3 D4 D5 D9 EC6 EC7 F1 L1 L5 NT1 Q1 R1 R2 R3 R4 R5 R7 R8 R10 R11 R12 R13 R14 R15 R17 R18 R19 R32 R34 R42 R43 R50 RT1 U2 U3 U5 U8

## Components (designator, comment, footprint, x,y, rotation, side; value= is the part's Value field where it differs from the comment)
C1 "SCC2220X333K252T" 2220_280 -21.99,-13.19 r180 top
C2 "C3216X7T2W104M160AA" 1206_180 -23.64,-21.61 r90 bottom value=0.1uF
C3 "GRM31BR72J102KW01L" 1206 -17.23,10.06 r270 top value=1000pF
C4 "TMK212BBJ106KG-T" 0805_HV 15.54,-2.17 r180 top value=10uF
C5 "GRM188R6YA225KA12D" 0603 11.82,9.44 r180 top value=2.2uF
C6 "TMK212BBJ106KG-T" 0805_HV 15.56,-0.83 r180 top value=10uF
C7 "XCAP DGCX 0.1uF" "XCAP DGXC 0.1UF" -10.625,-17.71 r0 top value=0.1uF
C8 "865230657014" 400V27uF_Laydown -25.07,-21.25 r180 top value=39uF
C9 "865230657014" 400V27uF_Laydown -25.33,6.93 r180 top value=39uF
C10 "GCM188R71E105KA64D" 0603S 23.32,-14.85 r270 bottom value=1uF
C11 "GRM155R61E225ME15D" 0402S 22.07,-15.41 r0 bottom value=2.2uF
C12 "GRM155R71H332KA01D" 0402S 19.85,-15.15 r0 bottom value=3300pF
C13 "885342207003" WCAP-CSMH_0805_L2W1.25H0.8_Reflow 15.09,3.85 r0 top
C14 "GRM155R71E153KA61D" 0402S 17.21,-14.64 r0 bottom value=0.015uF
C15 "GRM188R61E106KA73D" 0603S -19.99,-4.36 r180 bottom value=10uF
C16 "GRM155R71H331KA01D" 0402S -15.72,-1.22 r0 bottom value=330pF
C17 "C1608X7R1E105K080AB" 0603S 10.6,-16.7 r0 bottom value=1uF
C18 "GRM155R71H183KA12D" 0402S 10.12,-23.01 r270 top value=0.018uF
C19 "C3216X7T2W104M160AA" 1206_180 -19.73,4.92 r180 bottom value=0.1uF
C20 "GRM155R71H472KA01D" 0402S 10.17,-25.82 r0 bottom value=4700pF
C21 "885012205055" 0402S 10.15,-24.87 r0 bottom value=100pF
C22 "C3216X7T2W104M160AA" 1206_180 -19.64,7.17 r180 bottom value=0.1uF
C23 "GRM155R71E153KA61D" 0402S 19.09,-15.42 r0 top value=0.015uF
C26 "C0402C102J3RACTU" 0402S 16.72,-10.5 r180 bottom value=1000pF
C27 "885012205042" WCAP-CSGP_0402_L1W0.5H0.5 21.91,-10.47 r90 top
C28 "885012205042" WCAP-CSGP_0402_L1W0.5H0.5 22.95,-23.91 r180 bottom
C29 "885012205042" WCAP-CSGP_0402_L1W0.5H0.5 22.95,-19.5 r180 bottom
C30 "885012205042" WCAP-CSGP_0402_L1W0.5H0.5 18.82,-10.43 r90 top
C31 "CGA3E1X7R1E105K080AC" 0603S 16.838,11.84 r180 bottom value=1uF
C32 "TMY1102M" FP-TMY1102M_7854-MFG 2.806,-17.209 r0 top value=1nF
C38 "C1608X7R1V105K080AC" 0603S 14.74,-22.68 r270 top value=1uF
C49 "C3216X5R1E336M160AC" 1206_180 15.84,-1.57 r180 bottom value=33uF
D1 "Z4DGP406L-HF" FP-Z4DGP406L-HF_SMT_8MM1_10MM5-MFG -16.51,-21.8 r270 bottom
D2 "CDSOD323-T05C" SOD-323-Bi 22.21,-22.54 r180 bottom value=5V
D3 "MRA4007T3G" SMA -20.414,4.724 r315 top value=1000V
D4 "ES1JFL" SOD-123 -19.92,-11.62 r270 bottom value=600V
D5 "ES1JFL" SOD-123 -16.41,-11.69 r270 bottom value=600V
D6 "STS321050B331" FP-STS321050B331_SOD-323-MFG 17.78,-23.71 r180 bottom
D7 "CDSOD323-T05C" SOD-323-Bi 22.21,-20.82 r180 bottom value=5V
D8 "STS321050B331" FP-STS321050B331_SOD-323-MFG 18.07,-19.73 r0 bottom
D9 "BAV21W-7-F" SOD-123 11.9,11.55 r180 top value=200V
D13 "RB521SM-40T2R" SOD-523 13.64,-22.81 r270 top value=40V
EC6 "ECAP_LAYDOWN" CE05.5P254L11 17.02,0.52 r180 top value=470uF
EC7 "ECAP_LAYDOWN" CE05.5P254L11 16.84,-3.6 r180 top value=470uF
F1 "JFC2410-1400TS" FP-JFC2410-1400TS_SMT_FUSE_6MM1_2MM6-MFG -22.207,-6.954 r0 top
J4 "DX07S024JJ2R1300" JAE_DX07S024JJ2R1300 24.36,-21.205 r90 top
L1 "MNR-6045-680MTS" MNR-6045 -13.73,-12.45 r90 top value=68uH
L5 "MDM-9070F-102" FP-MDM-9070F-102_SMT_CMC_9MM0_7MM0-MFG -14.79,-21.581 r0 top
NT1 "Net-Tie" Net-Tie_10milWide_30milLong -19.029,-5.42 r0 bottom net-tie
Q1 "BSC093N15NS5ATMA1" PG-TDSON-8 14.465,5.355 r0 bottom value=150V
Q2 "CSD17575Q3" DQG0008A 17.67,-6.878 r90 bottom value=30V
R1 "CRCW0805470KJNEA" 0805_HV -16.8,10.24 r270 bottom value=470k
R2 "CRCW04021R10FKED" 0402S 11.48,-25.33 r270 bottom value=1.10
R3 "RC1206FR-0730RL" 1206 -21.43,9.22 r0 top value=30.0
R4 "CRCW04021R10FKED" 0402S 13.61,9.83 r270 top value=1.10
R5 "CRCW12064K70JNEA" 1206 -13.52,-11.63 r90 bottom value=4.7k
R7 "CRCW04027K68FKED" 0402S -17.73,-4.48 r90 bottom value=7.68k
R8 "CRCW040228K7FKED" 0402S -16.83,-4.47 r90 bottom value=28.7k
R9 "CRCW04022R20JNED" 0402S 23.44,-13.05 r270 bottom value=2.2
R10 "CRCW04023K01FKED" 0402S 10.57,-21.72 r180 top value=3.01k
R11 "RG1608P-433-B-T5" 0603 10.53,-18.11 r180 bottom value=43.0k
R12 "CRCW04021R10FKED" 0402S -15.18,-3.33 r270 bottom value=1.10
R13 "CRCW0402150RFKED" 0402S 11.03,-23.01 r270 top value=150
R14 "CRCW040215K0FKED" 0402S 8.28,-23.26 r270 bottom value=15.0k
R15 "RC0402FR-074K7L" 0402S 9,-25.38 r90 bottom value=4.70k
R17 "RC1206FR-0730RL" 1206 -21.46,11.25 r0 top value=30.0
R18 "CRCW04021R00JNED" 0402S 10.6,-25.3 r270 top value=1.0
R19 "RG1608P-333-B-T5" 0603 10.51,-19.72 r180 bottom value=33.0k
R21 "RC0402FR-071KL" 0402S 16.69,-11.36 r180 bottom value=1.00k
R22 "CSR1206-0R005F1" 1206 14.14,-11.08 r270 bottom value=0.005
R23 "ERJ-2RKF3301X" 0402S 17.21,-15.51 r0 bottom value=3.30k
R24 "CRCW04026R80JNED" 0402S 21.22,-23.9 r180 bottom value=6.8
R25 "CRCW04026R80JNED" 0402S 20.03,-22.62 r270 bottom value=6.8
R26 "CRCW040251K0JNED" 0402 23.41,-11.07 r90 bottom value=51k
R27 "CRCW04026R80JNED" 0402S 21.16,-19.53 r180 bottom value=6.8
R28 "CRCW04026R80JNED" 0402S 19.75,-18.69 r180 bottom value=6.8
R29 "ERJ-2RKF3301X" 0402S 19.09,-13.73 r0 top value=3.30k
R30 "MCR01MZPF1001" 0402S 20.89,-13.59 r270 top value=1.00k
R32 "RC0603FR-07300RL" 0603 19.01,7.73 r90 bottom value=300
R34 "CRCW060347K0FKEA" 0603S 13.51,10.35 r90 bottom value=47.0k
R35 "RC0402FR-07100KL" 0402S 17.18,-9.13 r0 bottom value=100k
R36 "ESR03EZPJ102" 0603S 23.15,-9.6 r90 top value=1.0k
R42 "CRCW040211K5FKED" 0402S -15.99,-4.48 r90 bottom value=11.5k
R43 "CRCW04025K23FKED" 0402S -15.67,-2.06 r180 bottom value=5.23k
R50 "CRCW060312R0JNEA" 0603 12.13,4.05 r0 top value=12
RT1 "NCP15WF104F03RC" 0402S -15.76,-0.4 r180 bottom value=100k
U1 "IP2723T" FP-IP2723TH_QFN24-IPC_C 20.114,-12.2 r90 bottom
U2 "ATL431AIDBZR" DBZ0003A_N 10.8,-22.42 r90 bottom
U3 "VOL618A-2T" SOP254P1020X230-4 3.72,-23.3 r180 top
U5 "MP6908GJ-Z" FP-MP6908GJ-Z_TSOT23-6-MFG 16.07,9.76 r0 bottom
U8 "UCG28682" REZ0012A-MFG -19.71,-0.64 r270 bottom

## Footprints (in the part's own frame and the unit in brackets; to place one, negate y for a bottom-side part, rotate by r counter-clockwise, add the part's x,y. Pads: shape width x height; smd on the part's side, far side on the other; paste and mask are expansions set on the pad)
400V27uF_Laydown [mm]
  oval 0.8x0.9 hole 0.6: 1(0,2.75) 2(0,-2.75)
  silkscreen extent -1.22,-5.23 22.5,5.25, body extent -0.06,-5.29 22.56,5.31, height 5
0402 [mm] "0402 from SM-752 data"
  rect 0.8x0.6 smd: 1(-0.6,0) 2(0.6,0)
  silkscreen extent -1.22,-0.52 1.22,0.52, body extent -0.55,-0.3 0.55,0.3, height 0.6
0402S [mil] "Based on C0402S footprint from PADS legacy"
  rect 15x24 smd: 1(-20,0) 2(20,0)
  body extent -22,-12 22,12, height 24
0603 [mm] "0603 from SM-752 data"
  rect 1x0.95 smd: 1(-0.8,0) 2(0.8,0)
  silkscreen extent -1.52,-0.69 1.52,0.69, body extent -0.87,-0.47 0.87,0.47, height 1
0603S [mil]
  rect 20x35 smd: 1(-30,0) 2(30,0)
  silkscreen extent -10,-17 10,17, body extent -34,-19 34,19, height 39
0805_HV [mil] "0805 with 30mil clearance between pads"
  rect 50x63 smd: 1(-40,0) 2(40,0)
  silkscreen extent -74,-40 74,40, body extent -43,-29 43,29, height 57
1206 [mm] "1206 from SM-752 data"
  rect 1.3x1.85 smd: 1(-1.45,0) 2(1.45,0)
  silkscreen extent -2.4,-1.21 2.4,1.21, body extent -1.7,-0.9 1.7,0.9, height 1.35
1206_180 [mm] "1206_180"
  rect 1.1x1.6 smd: 1(-1.7,0) 2(1.7,0)
  silkscreen extent -0.9,-1 0.9,1, body extent -1.75,-0.95 1.75,0.95, height 1.8
2220_280 [mm] "Chip Capacitor, Body 5.7x5.0mm, IPC Medium Density"
  rect 1.6x5.3 smd: 1(-2.6,0) 2(2.6,0)
  silkscreen extent -3.69,-2.94 3.69,2.94, body extent -2.95,-2.62 2.95,2.62, height 2.8
CE05.5P254L11 [mm]
  rect 1.2x1.2 hole 0.8: 1(0,0)
  round 1.2 hole 0.8: 2(2.54,0)
  silkscreen extent -1.48,-12.02 4.02,-1.02, body extent -1.23,-11.05 3.77,-1.05, height 5
DBZ0003A_N [mm] "SOT23, 3-Leads, Body 2.9x1.3mm, Pitch 0.95mm, Lead Span 2.4mm, IPC Medium Density"
  rrect17% 1x0.6 smd: 1(-1.2,0.95) 2(-1.2,-0.95) 3(1.2,0)
  silkscreen extent 0.2,-1.5 0.7,1.5, body extent -1.26,-1.46 1.26,1.46, height 0.98
DQG0008A [mm] "SMD, 8-Leads, Body 3.3x3.3mm, Pitch 0.65mm"
  rrect45% 0.75x0.44 smd paste-0.05 mask-0.05: 1(-1.525,0.975) 2(-1.525,0.325) 3(-1.525,-0.325) 4(-1.525,-0.975) 5(1.525,-0.975) 6(1.525,-0.325) 7(1.525,0.325) 8(1.525,0.975)
  rrect15% 0.676x1.125 on Bottom Paste: 9(-0.212,-0.663) 9(-0.212,0.662) 9(0.664,-0.663) 9(0.664,0.662)
  rrect6% 1.775x2.45 on Bottom Solder: 9(0.327,0)
  rrect8% 2.5x2.55 smd paste-1.5 mask-1.5: 9(0.65,0)
  rrect29% 0.5x0.34 on Bottom Solder: 9(1.175,-0.975) 9(1.175,-0.325) 9(1.175,0.975) 9(1.175,0.325)
  silkscreen extent -1.8,-1.8 1.8,1.8, body extent -1.65,-1.65 1.65,1.65, height 1.1
FP-IP2723TH_QFN24-IPC_C [mm]
  rrect42% 0.761x0.239 smd paste+0 mask+0: 1(-1.876,1.25)
  rrect100% 0.761x0.239 smd paste+0 mask+0: 2(-1.876,0.75) 3(-1.876,0.25) 4(-1.876,-0.25) 5(-1.876,-0.75) 6(-1.876,-1.25) 13(1.876,-1.25) 14(1.876,-0.75) 15(1.876,-0.25) 16(1.876,0.25) 17(1.876,0.75) 18(1.876,1.25)
  rrect100% 0.239x0.761 smd paste+0 mask+0: 7(-1.25,-1.876) 8(-0.75,-1.876) 9(-0.25,-1.876) 10(0.25,-1.876) 11(0.75,-1.876) 12(1.25,-1.876) 19(1.25,1.876) 20(0.75,1.876) 21(0.25,1.876) 22(-0.25,1.876) 23(-0.75,1.876) 24(-1.25,1.876)
  rrect4% 2.6x2.6 smd paste-1000 mask+0: 25(0,0)
  silkscreen extent -2.93,-2 2,2, body extent -2,-2 2,2, height 0.8
FP-JFC2410-1400TS_SMT_FUSE_6MM1_2MM6-MFG [mm] "Recommended Land Pattern"
  rrect5% 1.96x3.15 smd paste+0 mask+0: 1(-2.455,0) 2(2.455,0)
  silkscreen extent -1.1,-1.4 1.1,1.4, body extent -3.53,-1.68 3.53,1.68, height 0.25
FP-MDM-9070F-102_SMT_CMC_9MM0_7MM0-MFG [mm] "Recommended Land Pattern"
  rrect6% 3x1.75 smd paste+0 mask+0: 1(-4,1.625) 2(4,1.625) 3(-4,-1.625) 4(4,-1.625)
  silkscreen extent -6.17,-3.75 4.75,3.75, body extent -5.6,-3.85 5.6,3.85, height 0.25
FP-MP6908GJ-Z_TSOT23-6-MFG [mm]
  rrect17% 1.2x0.6 smd paste+0 mask+0: 1(-1.3,0.95) 2(-1.3,0) 3(-1.3,-0.95) 4(1.3,-0.95) 5(1.3,0) 6(1.3,0.95)
  silkscreen extent -2.52,-1.5 0.33,1.5, body extent -1.4,-1.45 1.4,1.45, height 1
FP-STS321050B331_SOD-323-MFG [mm]
  rrect13% 0.8x0.8 smd paste+0 mask+0: 1(-1.1,0) 2(1.1,0)
  silkscreen extent -0.33,-0.7 0.33,0.7, body extent -1.4,-0.65 1.4,0.65, height 1
FP-TMY1102M_7854-MFG [mm] "Recommended Land Pattern"
  rrect5% 2.2x3.6 smd paste+0 mask+0: 1(-5.1,0) 2(5.1,0)
  silkscreen extent -3.95,-2.75 3.95,2.75, body extent -4.8,-2.7 4.8,2.7, height 2.45
FP-Z4DGP406L-HF_SMT_8MM1_10MM5-MFG [mm]
  rrect4% 2.3x4.3 smd paste+0 mask+0: 1(2.55,3.85) 2(2.55,-3.85) 3(-2.55,-3.85) 4(-2.55,3.85)
  silkscreen extent -4.1,-5.3 4.1,6.67, body extent -4.05,-5.25 4.05,5.25, height 1.45
JAE_DX07S024JJ2R1300 [mm] "Receptacle, USB 3.1 Type C, R/A, SMT"
  rrect37% 0.27x0.9 smd: A1(-2.625,7.55) A2(-2.125,7.55) A3(-1.625,7.55) A4(-1.125,7.55) A5(-0.625,7.55) A6(-0.125,7.55) A7(0.375,7.55) A8(0.875,7.55) A9(1.375,7.55) A10(1.875,7.55) A11(2.375,7.55) A12(2.875,7.55)
  round 0.3 hole 0.6 unplated mask+0.102: ALIGN1(-3.6,4.85)
  rrect100% 0.55x0.3 hole 0.5 slot 0.85 at 0 deg unplated mask+0.102: ALIGN2(3.6,4.915)
  rrect37% 0.27x0.8 smd: B1(2.625,5.95) B2(2.125,5.95) B3(1.625,5.95) B4(1.125,5.95) B5(0.625,5.95) B6(0.125,5.95) B7(-0.375,5.95) B8(-0.875,5.95) B9(-1.375,5.95) B10(-1.875,5.95) B11(-2.375,5.95) B12(-2.875,5.95)
  rrect100% 1.2x2.3 hole 0.6 slot 1.9 at 90 deg: S1(-4.32,6.85) S2(4.32,6.85)
  rrect100% 1.45x1.1 hole 0.7 slot 1.25 at 0 deg: S1(-3.995,6.25) S2(3.995,6.25)
  rrect100% 1.3x2.6 hole 0.7 slot 2 at 90 deg: S3(-4.32,1.8) S4(4.32,1.8)
  body extent -4.47,-0.5 4.47,7.67, height 3.14
MNR-6045 [mm] "Mag.Layers P/N: MNR-6045-220MTS_Series"
  rect 1.6x5.7 smd: 1(-2.35,0) 2(2.35,0)
  silkscreen extent -3.4,-3.2 3.4,3.2, body extent -3.15,-3.15 3.15,3.15, height 4.5
Net-Tie_10milWide_30milLong [mil] "10mil net tie, no solder mask opening, no solder paste"
  rect 30x10 smd paste-5 mask-5: 1(-15,0) 2(15,0)
PG-TDSON-8 [mm] "Infineon recommended land pattern"
  rect 1.2x0.65 smd: 1(-2.825,1.905) 2(-2.825,0.635) 3(-2.825,-0.635) 4(-2.825,-1.905)
  rect 0.5x0.7 smd: 5(3.175,-2) 6(3.175,-0.675) 7(3.175,0.675) 8(3.175,2)
  rect 4.5x4.7 smd paste-2.25: 9(0.675,0)
  silkscreen extent -3.74,-3 3.74,3, body extent -3.17,-2.89 3.17,2.9, height 1.1
REZ0012A-MFG [mm]
  rrect29% 0.7x0.85 smd paste-1000 mask-1000: 1(-2.4,1.975)
  rrect29% 0.7x2.35 smd paste-1000 mask-1000: 2(-2.4,-1.225)
  rrect40% 0.25x0.6 smd paste+0 mask+0: 3(-0.225,-2.4) 4(0.275,-2.4) 5(0.775,-2.4) 6(1.275,-2.4) 7(1.775,-2.4)
  round 0.203 smd paste+0 mask+0: 8(2.288,-2.288)
  rrect40% 0.6x0.25 smd paste+0 mask+0: 9(2.4,-1.75) 10(2.4,-1.25) 11(2.4,-0.75)
  round 2.788 smd paste-1000 mask-1000: 12(1.199,1.048)
  Top Layer region: -0.45,2.65 -0.437,2.7 -0.4,2.737 -0.35,2.75 -0.35,2.75 2.648,2.75 2.698,2.737 2.735,2.7 2.748,2.65 2.748,2.65 2.748,-0.325 2.735,-0.375 2.698,-0.412 2.648,-0.425 2.648,-0.425 1.95,-0.425 1.931,-0.429 1.915,-0.44 1.904,-0.456 1.9,-0.475 1.9,-0.475 1.9,-1.8 1.887,-1.85 1.85,-1.887 1.8,-1.9 1.8,-1.9 -0.35,-1.9 -0.4,-1.887 -0.437,-1.85 -0.45,-1.8 -0.45,-1.8
  Top Layer region: 2.2,-2.7 2.175,-2.693 2.157,-2.675 2.15,-2.65 2.15,-2.65 2.15,-2.175 2.154,-2.156 2.165,-2.14 2.181,-2.129 2.2,-2.125 2.2,-2.125 2.65,-2.125 2.669,-2.129 2.685,-2.14 2.696,-2.156 2.7,-2.175 2.7,-2.175 2.7,-2.275 2.693,-2.3 2.675,-2.318 2.65,-2.325 2.65,-2.325 2.45,-2.325 2.412,-2.333 2.379,-2.354 2.358,-2.387 2.35,-2.425 2.35,-2.425 2.35,-2.65 2.343,-2.675 2.325,-2.693 2.3,-2.7 2.3,-2.7
  silkscreen extent -3.37,-2.55 -0.73,2.55, body extent -2.5,-2.5 2.5,2.5, height 1
SMA [mm] "Molded Diode, 2-Leads, Body 4.3x2.6mm, IPC Medium Density, based on OnSemi component dimensions and land pattern"
  rect 2x2 smd: 1(-2,0) 2(2,0)
  silkscreen extent -3.66,-1.57 2.79,1.58, body extent -2.6,-1.3 2.6,1.3, height 2.42
SOD-123 [mm] "On Semi recommended land pattern"
  rect 0.915x1.22 smd: 1(-1.637,0) 2(1.637,0)
  silkscreen extent -2.74,-1.17 2.03,1.17, body extent -1.93,-0.9 1.93,0.9, height 1.35
SOD-323-Bi [mm] "SOD323, 2-Leads, Body 1.9x1.45mm, No Polarity Mark"
  rect 0.6x0.6 smd paste-0.05: 1(-1.1,0) 2(1.1,0)
  silkscreen extent -1.53,-0.77 1.53,0.77, body extent -1.27,-0.65 1.27,0.65, height 1.02
SOD-523 [mm] "NXP Semiconductor recommended land pattern, nominal STEP model"
  rect 0.8x0.6 smd paste-0.05: 1(-0.55,0) 2(0.55,0)
  silkscreen extent -1.65,-0.66 1.2,0.66, body extent -0.8,-0.4 0.8,0.4, height 0.72
SOP254P1020X230-4 [mm] "VISHAY"
  rect 1.3x0.9 smd: 1(-4.75,1.27) 2(-4.75,-1.27) 3(4.75,-1.27) 4(4.75,1.27)
  body extent -3.85,-2.05 3.85,2.05, height 2.02
WCAP-CSGP_0402_L1W0.5H0.5 [mm] "Ceramic Capacitors, body 1x0.5mm"
  rect 0.5x0.5 smd: 1(-0.5,0) 2(0.5,0)
  body extent -0.5,-0.25 0.5,0.25, height 0.5
WCAP-CSMH_0805_L2W1.25H0.8_Reflow [mm] "Ceramic Capacitors, body 2x1.25mm"
  rect 0.9x1.3 smd: 1(-0.95,0) 2(0.95,0)
  body extent -1,-0.63 1,0.62, height 0.8
"XCAP DGXC 0.1UF" [mm]
  oval 0.8x0.9 hole 0.6: 1(0,0) 2(0,-7.4)
  silkscreen extent 0,-8.66 10.03,1.19

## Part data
C1: library part CMP-0112463-1, "2220 SMD, 33nF, 250VAC, Holley Stone", Capacitance Tolerance=+/-10%, Insulation Resistance=30000MOhm, Manufacturer="Holley Stone", Manufacturer Part Number=890324023028, Operating Temperature Max=105°C, Operating Temperature Min=-40°C, Rate of Voltage Rise=300V/us, Rated Voltage (AC)=275V
C2 C19 C22: library part CMP-0008729-1, "CAP, CERM, 0.1 uF, 450 V, +/- 20%, X7T, 1206", Cap_Case=1206, Manufacturer=TDK, Supplier Part Number 1=445-14838-1-ND, TempCo=X7T, Tolerance_%=20%, Value1=Unknown, Value2=450V, ValueDisplayed=0.1uF
C3: library part CMP-0008909-2, "CAP, CERM, 1000 pF, 630 V, +/- 10%, X7R, 1206", Cap_Case=1206, Manufacturer=MuRata, Supplier Part Number 1=490-3506-1-ND, TempCo=X7R, Tolerance_%=10%, Value1=Unknown, Value2=630V, ValueDisplayed=1000pF
C4 C6: library part CMP-0008414-2, "CAP, CERM, 10 uF, 25 V, +/- 10%, X5R, 0805", Cap_Case=0805, Manufacturer="Taiyo Yuden", Supplier Part Number 1=587-2985-1-ND, TempCo=X5R, Tolerance_%=10%, Value1=Unknown, Value2=25V, ValueDisplayed=10uF
C5: library part CMP-0007356-4, "CAP, CERM, 2.2 uF, 35 V, +/- 10%, X5R, 0603", Cap_Case=0603, Manufacturer=MuRata, Supplier Part Number 1=490-7204-6-ND, TempCo=X5R, Tolerance_%=10%, Value1=Unknown, Value2=35V, ValueDisplayed=2.2uF
C7: PartNumber=MX2224KQ3B40YC3F00R
C8 C9: "Aluminum Electrolytic Capacitor, Radial, THT, D10 x H20-mm, 39µF, 400V", Capacitance Tolerance=+0%/-40%, Case/Size Code="D10 x H20mm", Leakage Current=264uA, Manufacturer=Yongming, Operating Temperature Max=105°C, Operating Temperature Min=-25°C, PartNumber=KCXE2502G470MF, Rated Voltage (DC)=400V, Ripple Current=200mA
C10: library part CMP-0007139-1, "CAP, CERM, 1 uF, 25 V, +/- 10%, X7R, AEC-Q200 Grade 1, 0603", Cap_Case=0603, Manufacturer=MuRata, Supplier Part Number 1=490-10673-1-ND, TempCo=X7R, Tolerance_%=10%, Value1=Unknown, Value2=25V, ValueDisplayed=1uF
C11: library part CMP-0081010-1, "CAP, CERM, 2.2 µF, 25 V,+/- 20%, X5R, 0402", Cap_Case=0402, Manufacturer=MuRata, Supplier Part Number 1=490-10457-1-ND, TempCo=X5R, Tolerance_%=20%, Value2=25V, ValueDisplayed=2.2µF
C12: library part CMP-0006688-2, "CAP, CERM, 3300 pF, 50 V, +/- 10%, X7R, 0402", Cap_Case=0402, Manufacturer=MuRata, Supplier Part Number 1=490-3248-1-ND, TempCo=X7R, Tolerance_%=10%, Value1=Unknown, Value2=50V, ValueDisplayed=3300pF
C13: library part CMP-0112285-1, "WCAP-CSMH Multilayer Ceramic Chip Capacitor, Mid and High Voltage, size 0805, X7R Class II, 1nF, 200VDC", Capacitance Tolerance=10%, Case/Size Code=0805, Insulation Resistance=10GOhm, Manufacturer="Wurth Elektronik", Operating Temperature Max=125°C, Operating Temperature Min=-55°C, Rated Voltage (DC)=200V
C14 C23: library part CMP-0006661-1, "CAP, CERM, 0.015 uF, 25 V, +/- 10%, X7R, 0402", Cap_Case=0402, Manufacturer=MuRata, Supplier Part Number 1=490-3251-1-ND, TempCo=X7R, Tolerance_%=10%, Value1=Unknown, Value2=25V, ValueDisplayed=0.015uF
C15: library part CMP-0860569-1, "CAP, CERM, 10 µF, 25 V,+/- 10%, X5R, 0603", Cap_Case=0603, Manufacturer=MuRata, TempCo=X5R, Tolerance_%=10%, Value2=25V, ValueDisplayed=10µF
C16: library part CMP-0006687-2, "CAP, CERM, 330 pF, 50 V, +/- 10%, X7R, 0402", Cap_Case=0402, Manufacturer=MuRata, Supplier Part Number 1=490-3247-1-ND, TempCo=X7R, Tolerance_%=10%, Value1=Unknown, Value2=50V, ValueDisplayed=330pF
C17: library part CMP-0007040-4, "CAP, CERM, 1 µF, 25 V, +/- 10%, X7R, 0603", Cap_Case=0603, Manufacturer=TDK, Supplier Part Number 1=445-5956-1-ND, TempCo=X7R, Tolerance_%=10%, Value1=Unknown, Value2=25V, ValueDisplayed=1uF
C18: library part CMP-0006681-2, "CAP, CERM, 0.018 uF, 50 V, +/- 10%, X7R, 0402", Cap_Case=0402, Manufacturer=MuRata, Supplier Part Number 1=GRM155R71H183KA12D-ND, TempCo=X7R, Tolerance_%=10%, Value1=Unknown, Value2=50V, ValueDisplayed=0.018uF
C20: library part CMP-0006692-2, "CAP, CERM, 4700 pF, 50 V, +/- 10%, X7R, 0402", Cap_Case=0402, Manufacturer=MuRata, Supplier Part Number 1=490-1308-1-ND, TempCo=X7R, Tolerance_%=10%, Value1=Unknown, Value2=50V, ValueDisplayed=4700pF
C21: library part CMP-0006230-2, "CAP, CERM, 100 pF, 50 V, +/- 10%, X7R, 0402", Cap_Case=0402, Manufacturer="Wurth Elektronik", Supplier Part Number 1=732-7550-1-ND, TempCo=X7R, Tolerance_%=10%, Value1=Unknown, Value2=50V, ValueDisplayed=100pF
C26: library part CMP-0006234-2, "CAP, CERM, 1000 pF, 25 V, +/- 5%, X7R, 0402", Cap_Case=0402, Manufacturer=Kemet, Supplier Part Number 1=399-7752-1-ND, TempCo=X7R, Tolerance_%=5%, Value1=Unknown, Value2=25V, ValueDisplayed=1000pF
C27 C28 C29 C30: library part CMP-0104610-1, "WCAP-CSGP Multilayer Ceramic Chip Capacitor, General Purpose, size 0402, X7R, 470pF, 25VDC", Capacitance Tolerance=+/-10%, Case/Size Code=0402, Insulation Resistance=10GOhm, Manufacturer="Wurth Elektronik", Operating Temperature Max=125°C, Operating Temperature Min=-55°C, Rated Voltage (DC)=25V
C31: library part CMP-0076705-1, "CAP, CERM, 1 µF, 25 V,+/- 10%, X7R, AEC-Q200 Grade 1, 0603", Cap_Case=1.6x0.8x0.8mm, Manufacturer=TDK, Supplier Part Number 1=445-6931-1-ND, TempCo=X7R, Tolerance_%=10%, Value2=25V, ValueDisplayed=1µF
C32: library part CMP-0125632-1, "SMD-Y1 a.c. ceramic capacitor 1000pF 20% 400VAC 7.8x5.4x2.45mm", Manufacturer="SICHUAN TRX TECHNOLOGY", Operating Temperature Range="-40°C to +125°C", TempCo=+22/-56%, Temperature Characteristic=Y5U, Tolerance_%=20%, ValueDisplayed=1000pF
C38: library part CMP-0007052-2, "CAP, CERM, 1 uF, 35 V, +/- 10%, X7R, 0603", Cap_Case=0603, Manufacturer=TDK, Supplier Part Number 1=445-7414-1-ND, TempCo=X7R, Tolerance_%=10%, Value1=Unknown, Value2=35V, ValueDisplayed=1uF
C49: library part CMP-0008655-1, "CAP, CERM, 33 uF, 25 V, +/- 20%, X5R, 1206", Cap_Case=1206_180, Manufacturer=TDK, Supplier Part Number 1=445-8046-1-ND, TempCo=X5R, Tolerance_%=20%, Value1="0.002648 ohm", Value2=25V, ValueDisplayed=33uF
D1: library part CMP-0120719-1, "Bridge Rectifier Single Phase Standard 600 V Surface Mount Z4-D", Digikey Part Number=641-1502-1-ND, Forward Current=4A, Manufacturer=Comchip, Max Surge Forward Current=150A, Mouser Part Number=750-Z4DGP406L-HF, Operating Temperature Range="-55°C to +175°C", Peak Reverse Current=0.08uA, ValueDisplayed=45pF
D2 D7: library part CMP-0006065-2, "Diode, TVS, Bi, 5 V, SOD323, 2-Leads, Body 1.9x1.45mm, No Polarity Mark", Manufacturer=Bourns, Value1=350W
D3: library part CMP-0077082-2, "Diode, Standard Recovery Rectifier, 1000 V, 1 A, AEC-Q101, SMA", Manufacturer="ON Semiconductor", Value1=1A, Value2=1.1V
D4 D5: library part CMP-0029032-2, "Diode, Switching, 600 V, 1 A, SOD-123", Manufacturer="ON Semiconductor", Supplier Part Number 1=ES1JFLDKR-ND, Value1=1A, Value2=1V
D6 D8: library part CMP-0092592-1, "18V Clamp 22A (8/20µs) Ipp Tvs Diode Surface Mount SOD-323", Breakdown Voltage=5.5V, Clamping Voltage=18V, Digikey Part Number=283-STS321050B331CT-ND, Manufacturer=Eaton, Mouser Part Number=504-STS321050B331, Operating Temperature Range="-55°C to +125°C", ValueDisplayed=33pF
D9: library part CMP-0029031-2, "Diode, Switching, 200 V, 0.2 A, SOD-123", Manufacturer="Diodes Inc.", Value1=0.2A, Value2=1.25V
D13: library part CMP-0074704-3, "Diode, Schottky, 40 V, 0.2 A, SOD-523", Manufacturer=Rohm, Supplier Part Number 1=RB521SM-40T2RDKR-ND, Value1=0.2A, Value2=0.54V
EC6 EC7: "25V/470uF D5.5*11mm", Voltage=25V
